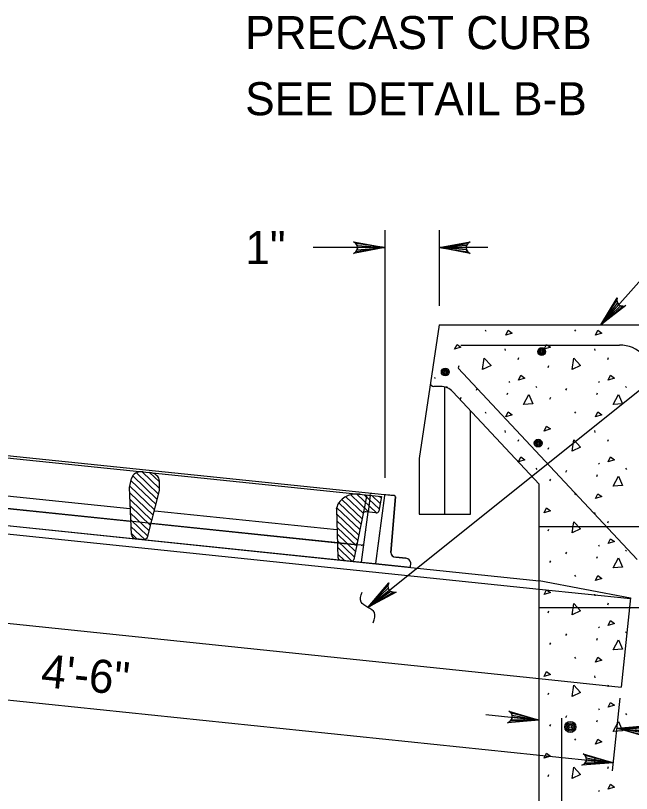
# Model space of a CAD drawing. Extents: x 2.4 to 9.7, y 1.1 to 11.2.
# Drawn here: x 3.54 to 4.657, y 9.657 to 11.069 of the extents above; entities that cross this region are included whole.
import ezdxf

# ---------------------------------------------------------------- set-up
doc = ezdxf.new("R2010")
doc.units = 0
for name, color, linetype in [('DETL-DIMS', 7, 'Continuous'), ('DETL-LINE', 7, 'Continuous'), ('DETL-NOTE', 7, 'Continuous'), ('DETL-PATT', 7, 'Continuous')]:
    doc.layers.add(name, color=color, linetype=linetype)

msp = doc.modelspace()

# ---------------------------------------------------------------- linework, layer by layer
at = {"layer": 'DETL-DIMS'}
for p, q in [((4.6016, 10.5079), (4.967, 10.9182)), ((4.2096, 10.6797), (4.2096, 10.2304)), ((4.3082, 10.6797), (4.3082, 10.5422)), ((4.2096, 10.648), (4.0797, 10.648)), ((4.3967, 10.648), (4.3082, 10.648)), ((4.179, 9.9951), (4.8454, 10.5282)), ((2.8155, 9.9012), (4.6246, 9.7131)), ((4.6231, 9.6985), (4.6368, 9.83)), ((4.393, 9.8005), (4.49, 9.7904)), ((4.6311, 9.7757), (4.9644, 9.7411))]:
    msp.add_line(p, q, dxfattribs=at)
for points in [[(4.2096, 10.648), (4.1531, 10.6374), (4.1575, 10.6404), (4.1597, 10.6442), (4.1604, 10.648), (4.1597, 10.6518), (4.1575, 10.6555), (4.1531, 10.6586), (4.2096, 10.648), (4.1575, 10.6555), (4.1597, 10.6518), (4.2096, 10.648), (4.1604, 10.648), (4.1597, 10.6442), (4.2096, 10.648), (4.1575, 10.6404)], [(4.3082, 10.648), (4.3647, 10.6586), (4.3603, 10.6555), (4.3581, 10.6518), (4.3574, 10.648), (4.3581, 10.6442), (4.3603, 10.6404), (4.3647, 10.6374), (4.3082, 10.648), (4.3603, 10.6404), (4.3581, 10.6442), (4.3082, 10.648), (4.3574, 10.648), (4.3581, 10.6518), (4.3082, 10.648), (4.3603, 10.6555)], [(4.6016, 10.5079), (4.6313, 10.5571), (4.6306, 10.5519), (4.632, 10.5477), (4.6344, 10.5447), (4.6376, 10.5426), (4.6419, 10.5418), (4.6471, 10.543), (4.6016, 10.5079), (4.6419, 10.5418), (4.6376, 10.5426), (4.6016, 10.5079), (4.6344, 10.5447), (4.632, 10.5477), (4.6016, 10.5079), (4.6306, 10.5519)], [(4.1798, 9.9955), (4.217, 10.0393), (4.2155, 10.0342), (4.2161, 10.0299), (4.218, 10.0265), (4.2209, 10.024), (4.225, 10.0225), (4.2303, 10.0229), (4.1798, 9.9955), (4.225, 10.0225), (4.2209, 10.024), (4.1798, 9.9955), (4.218, 10.0265), (4.2161, 10.0299), (4.1798, 9.9955), (4.2155, 10.0342)], [(4.49, 9.7904), (4.4327, 9.7857), (4.4374, 9.7883), (4.44, 9.7918), (4.441, 9.7955), (4.4408, 9.7993), (4.4389, 9.8033), (4.4349, 9.8068), (4.49, 9.7904), (4.4389, 9.8033), (4.4408, 9.7993), (4.49, 9.7904), (4.441, 9.7955), (4.44, 9.7918), (4.49, 9.7904), (4.4374, 9.7883)], [(4.6311, 9.7757), (4.6884, 9.7804), (4.6838, 9.7779), (4.6811, 9.7743), (4.6801, 9.7706), (4.6804, 9.7668), (4.6822, 9.7628), (4.6862, 9.7594), (4.6311, 9.7757), (4.6822, 9.7628), (4.6804, 9.7668), (4.6311, 9.7757), (4.6801, 9.7706), (4.6811, 9.7743), (4.6311, 9.7757), (4.6838, 9.7779)], [(4.6246, 9.7131), (4.5673, 9.7084), (4.572, 9.711), (4.5746, 9.7145), (4.5756, 9.7182), (4.5754, 9.7221), (4.5736, 9.7261), (4.5695, 9.7295), (4.6246, 9.7131), (4.5736, 9.7261), (4.5754, 9.7221), (4.6246, 9.7131), (4.5756, 9.7182), (4.5746, 9.7145), (4.6246, 9.7131), (4.572, 9.711)]]:
    msp.add_lwpolyline(points, dxfattribs=at)
msp.add_spline([(4.1885, 9.9672), (4.1911, 9.9855), (4.1667, 10.0048), (4.1685, 10.0227)], degree=3, dxfattribs=at)
at = {"layer": 'DETL-LINE'}
for p, q in [((4.3082, 10.5076), (4.2721, 10.2655)), ((4.3082, 10.5076), (4.7324, 10.5076)), ((4.348, 10.4712), (4.6355, 10.4712)), ((4.6678, 10.0818), (4.3432, 10.4289)), ((4.311, 10.3961), (4.2986, 10.3961)), ((4.3189, 10.1641), (4.3189, 10.395)), ((4.49, 10.2187), (4.3331, 10.3864)), ((4.3656, 10.1641), (4.3656, 10.3516)), ((2.9528, 10.3296), (4.2267, 10.1978)), ((4.2721, 10.2655), (4.2721, 10.1641)), ((3.7591, 10.2391), (3.7995, 10.2005)), ((3.7693, 10.2411), (3.8012, 10.2107)), ((3.783, 10.2399), (3.8011, 10.2227)), ((2.7749, 10.2215), (4.49, 10.0432)), ((4.1545, 10.1091), (3.0052, 10.228)), ((3.7494, 10.2247), (3.7947, 10.1815)), ((3.7524, 10.2336), (3.7971, 10.191)), ((2.8008, 10.2184), (4.2566, 10.0678)), ((3.7472, 10.2149), (3.7922, 10.1719)), ((4.49, 8.8182), (4.49, 10.2187)), ((3.7472, 10.2031), (3.7898, 10.1624)), ((4.1392, 10.1959), (4.1709, 10.1656)), ((4.1481, 10.1992), (4.1809, 10.1679)), ((4.1591, 10.2006), (4.1946, 10.1667)), ((4.1773, 10.1991), (4.1708, 10.1654)), ((4.1726, 10.1996), (4.1998, 10.1736)), ((4.1833, 10.1985), (4.1794, 10.1681)), ((4.1833, 10.1985), (4.1836, 10.2004)), ((4.1865, 10.1981), (4.2017, 10.1836)), ((4.2092, 10.1978), (4.1927, 10.0744)), ((4.2092, 10.1978), (4.1927, 10.0744)), ((4.2004, 10.1967), (4.2036, 10.1936)), ((4.2267, 10.1978), (4.2118, 10.1994)), ((4.229, 10.1957), (4.2207, 10.0943)), ((4.2208, 10.0946), (4.229, 10.1957)), ((3.0173, 10.1815), (4.49, 10.0284)), ((3.7477, 10.1908), (3.7874, 10.1529)), ((4.1263, 10.1845), (4.1668, 10.146)), ((4.1319, 10.191), (4.1688, 10.1558)), ((3.7482, 10.1785), (3.785, 10.1434)), ((3.7487, 10.1661), (3.7825, 10.1339)), ((4.1228, 10.176), (4.1647, 10.1361)), ((4.1676, 10.077), (4.1794, 10.1681)), ((3.7492, 10.1538), (3.7801, 10.1243)), ((4.1227, 10.1643), (4.1626, 10.1262)), ((4.123, 10.1522), (4.1606, 10.1163)), ((4.2721, 10.1641), (4.3656, 10.1641)), ((3.7498, 10.1415), (3.7738, 10.1186)), ((4.1234, 10.14), (4.1585, 10.1065)), ((4.49, 10.1416), (4.7324, 10.1416)), ((3.7503, 10.1292), (3.7608, 10.1191)), ((4.1237, 10.1279), (4.1565, 10.0966)), ((4.1237, 10.1123), (4.1286, 10.1118)), ((4.1241, 10.1157), (4.1544, 10.0867)), ((4.1286, 10.1118), (4.1545, 10.1091)), ((4.1667, 10.1079), (4.1545, 10.1091)), ((4.1244, 10.1035), (4.15, 10.0791)), ((4.1247, 10.0914), (4.1364, 10.0802)), ((4.2477, 10.0841), (4.2298, 10.086)), ((4.2298, 10.086), (4.2477, 10.0841)), ((4.2566, 10.0678), (4.2568, 10.0759)), ((4.49, 10.0441), (4.6558, 10.0126)), ((4.49, 10.0284), (4.6556, 10.0112)), ((3.0173, 10.0188), (4.49, 9.8657)), ((4.6558, 10.0126), (4.6389, 9.8503)), ((4.49, 9.9951), (4.7324, 9.9951)), ((4.49, 9.8657), (4.6389, 9.8503)), ((4.531, 8.6833), (4.531, 9.7941))]:
    msp.add_line(p, q, dxfattribs=at)
msp.add_lwpolyline([(4.1927, 10.0744), (4.2566, 10.0678), (4.2568, 10.0759)], dxfattribs=at)
for centre, radius in [((4.4944, 10.4593), 0.00707), ((4.4944, 10.4593), 0.0053), ((4.4944, 10.4593), 0.00354), ((4.4944, 10.4593), 0.00177), ((4.3195, 10.4221), 0.00707), ((4.3195, 10.4221), 0.0053), ((4.3195, 10.4221), 0.00354), ((4.3195, 10.4221), 0.00177), ((4.4881, 10.2932), 0.00707), ((4.4881, 10.2932), 0.0053), ((4.4881, 10.2932), 0.00354), ((4.4881, 10.2932), 0.00177), ((4.5464, 9.7781), 0.0101), ((4.5464, 9.7781), 0.00758), ((4.5464, 9.7781), 0.00505), ((4.5464, 9.7781), 0.00253)]:
    msp.add_circle(centre, radius, dxfattribs=at)
for centre, radius, start, end in [((4.6355, 10.4106), 0.0606, 0, 90), ((4.2986, 10.4021), 0.00606, 171.5077, 270), ((4.311, 10.3657), 0.0303, 43.0821, 90)]:
    msp.add_arc(centre, radius, start, end, dxfattribs=at)
for centre, major_axis, start_param, end_param in [((4.1861, 10.2001), (0.00246, -0.00025), 1.56959, 3.120609), ((4.2116, 10.1975), (0.00246, -0.00025), 1.56959, 3.117735), ((4.2116, 10.1975), (0.00246, -0.00025), 1.56959, 3.117735), ((4.2265, 10.1959), (0.00246, -0.00025), 0.016408, 1.56959), ((4.2265, 10.1959), (0.00246, -0.00025), 0.016408, 1.56959), ((4.129, 10.1156), (0.00492, -0.0005), 3.227653, 4.711182), ((4.1548, 10.1129), (0.00492, -0.0005), 4.711182, 6.215411), ((4.1671, 10.1117), (0.00492, -0.0005), 4.711182, 6.261981), ((4.2306, 10.0936), (0.00984, -0.00101), 3.144452, 4.711182), ((4.2306, 10.0936), (0.00984, -0.00101), 3.171548, 4.711182), ((4.2469, 10.0765), (0.00984, -0.00101), 0.060618, 1.56959), ((4.2469, 10.0765), (0.00984, -0.00101), 0.060618, 1.56959)]:
    msp.add_ellipse(centre, major_axis=major_axis, ratio=0.773781, start_param=start_param, end_param=end_param, dxfattribs=at)
at = {"layer": 'DETL-NOTE'}
for p, q in [((2.9746, 10.3235), (4.2041, 10.1963)), ((3.7468, 10.2129), (3.7504, 10.2292)), ((3.8012, 10.2072), (3.8011, 10.224)), ((3.4169, 10.2085), (3.7475, 10.1743)), ((3.7504, 10.1272), (3.7468, 10.2129)), ((3.7801, 10.1241), (3.8012, 10.2072)), ((3.8012, 10.2072), (3.8012, 10.2072)), ((4.2041, 10.1963), (4.199, 10.1697)), ((4.2267, 10.1978), (4.2267, 10.1978)), ((3.4117, 10.186), (3.747, 10.1513)), ((4.1236, 10.1857), (4.1236, 10.1857)), ((4.1228, 10.1355), (3.7925, 10.1697)), ((4.1224, 10.174), (4.123, 10.1766)), ((4.1224, 10.174), (4.1249, 10.0849)), ((4.1224, 10.174), (4.1224, 10.174)), ((4.1708, 10.1654), (4.1535, 10.0821)), ((4.1937, 10.1666), (4.1761, 10.1684)), ((4.2054, 10.161), (4.2054, 10.161)), ((3.7883, 10.147), (4.1237, 10.1123)), ((4.1713, 10.1422), (4.1713, 10.1422)), ((4.1768, 10.1348), (4.1768, 10.1348)), ((4.1975, 10.1328), (4.1975, 10.1328)), ((4.1982, 10.1272), (4.1982, 10.1272)), ((3.7695, 10.1182), (3.7594, 10.1192)), ((4.1274, 10.1084), (4.1274, 10.1084)), ((4.1571, 10.1172), (4.1571, 10.1172)), ((4.2003, 10.1123), (4.2003, 10.1123)), ((4.22, 10.1102), (4.22, 10.1102)), ((4.1295, 10.081), (4.1482, 10.079)), ((4.2477, 10.0841), (4.2477, 10.0841)), ((4.2566, 10.0678), (4.2566, 10.0678))]:
    msp.add_line(p, q, dxfattribs=at)
for centre, major_axis, start_param, end_param in [((3.7698, 10.2259), (0.0197, -0.002), 1.56959, 3.05312), ((3.7813, 10.2247), (0.0197, -0.002), 0.08606, 1.56959), ((4.1619, 10.1699), (0.0394, -0.004), 1.56959, 3.05312), ((4.1757, 10.1646), (0.00492, -0.0005), 1.56959, 3.073818), ((4.1941, 10.1704), (0.00492, -0.0005), 4.711182, 6.215411), ((3.7602, 10.1268), (0.00984, -0.00101), 3.223527, 4.711182), ((3.7703, 10.1258), (0.00984, -0.00101), 4.711182, 6.198838), ((4.1299, 10.0848), (0.00492, -0.0005), 3.227653, 4.711182), ((4.1486, 10.0828), (0.00492, -0.0005), 4.711182, 6.215411)]:
    msp.add_ellipse(centre, major_axis=major_axis, ratio=0.773781, start_param=start_param, end_param=end_param, dxfattribs=at)
at = {"layer": 'DETL-PATT'}
for p, q in [((4.3917, 10.4986), (4.3933, 10.4962)), ((4.5542, 10.4986), (4.5558, 10.4962)), ((4.4279, 10.4644), (4.4283, 10.4612)), ((4.5904, 10.4644), (4.5908, 10.4612)), ((4.4519, 10.445), (4.4531, 10.4483)), ((4.6144, 10.445), (4.6156, 10.4483)), ((4.3438, 10.4306), (4.345, 10.4338)), ((4.5063, 10.4306), (4.5075, 10.4338)), ((4.4348, 10.4052), (4.436, 10.4032)), ((4.5973, 10.4052), (4.5985, 10.4032)), ((4.3216, 10.3959), (4.3233, 10.3939)), ((4.376, 10.3891), (4.3776, 10.3923)), ((4.4841, 10.3959), (4.4858, 10.3939)), ((4.5385, 10.3891), (4.5401, 10.3923)), ((4.6466, 10.3959), (4.6483, 10.3939)), ((4.347, 10.3731), (4.3486, 10.3763)), ((4.4319, 10.3812), (4.4332, 10.3844)), ((4.5095, 10.3731), (4.5111, 10.3763)), ((4.5944, 10.3812), (4.5957, 10.3844)), ((4.3917, 10.3502), (4.3933, 10.3477)), ((4.5542, 10.3502), (4.5558, 10.3477)), ((4.4279, 10.3159), (4.4283, 10.3127)), ((4.5904, 10.3159), (4.5908, 10.3127)), ((4.4519, 10.2966), (4.4531, 10.2998)), ((4.6144, 10.2966), (4.6156, 10.2998)), ((4.5063, 10.2821), (4.5075, 10.2853)), ((4.5973, 10.2568), (4.5985, 10.2547)), ((4.4841, 10.2475), (4.4858, 10.2455)), ((4.5385, 10.2407), (4.5401, 10.2439)), ((4.5944, 10.2327), (4.5957, 10.2359)), ((4.6466, 10.2475), (4.6483, 10.2455)), ((4.5095, 10.2247), (4.5111, 10.2279)), ((4.5542, 10.2017), (4.5558, 10.1993)), ((4.5904, 10.1675), (4.5908, 10.1643)), ((4.6144, 10.1482), (4.6156, 10.1514)), ((4.5063, 10.1337), (4.5075, 10.1369)), ((4.5973, 10.1083), (4.5985, 10.1063)), ((4.5385, 10.0922), (4.5401, 10.0954)), ((4.6466, 10.0991), (4.6483, 10.097)), ((4.5944, 10.0843), (4.5957, 10.0875)), ((4.5095, 10.0762), (4.5111, 10.0794)), ((4.5542, 10.0533), (4.5558, 10.0509)), ((4.5904, 10.0191), (4.5908, 10.0158)), ((4.6144, 9.9997), (4.6156, 10.003)), ((4.5063, 9.9852), (4.5075, 9.9885)), ((4.5973, 9.9599), (4.5985, 9.9579)), ((4.5385, 9.9438), (4.5401, 9.947)), ((4.5944, 9.9358), (4.5957, 9.9391)), ((4.6466, 9.9506), (4.6483, 9.9486)), ((4.5095, 9.9278), (4.5111, 9.931)), ((4.5542, 9.9048), (4.5558, 9.9024)), ((4.5904, 9.8706), (4.5908, 9.8674)), ((4.6144, 9.8513), (4.6156, 9.8545)), ((4.5063, 9.8368), (4.5075, 9.84)), ((4.5385, 9.7953), (4.5401, 9.7986)), ((4.5973, 9.8114), (4.5985, 9.8094)), ((4.6466, 9.8022), (4.6483, 9.8002)), ((4.5944, 9.7874), (4.5957, 9.7906)), ((4.5095, 9.7794), (4.5111, 9.7826)), ((4.5542, 9.7564), (4.5558, 9.754)), ((4.5904, 9.7222), (4.5908, 9.719)), ((4.6144, 9.7029), (4.6156, 9.7061)), ((4.5063, 9.6884), (4.5075, 9.6916)), ((4.5973, 9.663), (4.5985, 9.661))]:
    msp.add_line(p, q, dxfattribs=at)
for points in [[(4.4295, 10.4893), (4.4336, 10.4982), (4.4408, 10.493), (4.4295, 10.4893)], [(4.592, 10.4893), (4.5961, 10.4982), (4.6033, 10.493), (4.592, 10.4893)], [(4.3365, 10.4636), (4.341, 10.4724), (4.3478, 10.4672), (4.3365, 10.4636)], [(4.499, 10.4636), (4.5035, 10.4724), (4.5103, 10.4672), (4.499, 10.4636)], [(4.3873, 10.4269), (4.3901, 10.4475), (4.4026, 10.4342), (4.3873, 10.4269)], [(4.5498, 10.4269), (4.5526, 10.4475), (4.5651, 10.4342), (4.5498, 10.4269)], [(4.3, 10.4123), (4.3015, 10.4112), (4.2998, 10.4107)], [(4.4523, 10.4076), (4.4568, 10.4165), (4.464, 10.4112), (4.4523, 10.4076)], [(4.6148, 10.4076), (4.6193, 10.4165), (4.6265, 10.4112), (4.6148, 10.4076)], [(4.4616, 10.3634), (4.4713, 10.3816), (4.4785, 10.3646), (4.4616, 10.3634)], [(4.6241, 10.3634), (4.6338, 10.3816), (4.641, 10.3646), (4.6241, 10.3634)], [(4.4295, 10.3409), (4.4336, 10.3498), (4.4408, 10.3445), (4.4295, 10.3409)], [(4.592, 10.3409), (4.5961, 10.3498), (4.6033, 10.3445), (4.592, 10.3409)], [(4.499, 10.3151), (4.5035, 10.324), (4.5103, 10.3188), (4.499, 10.3151)], [(4.5498, 10.2785), (4.5526, 10.299), (4.5651, 10.2857), (4.5498, 10.2785)], [(4.4523, 10.2592), (4.4568, 10.268), (4.464, 10.2628), (4.4523, 10.2592)], [(4.6148, 10.2592), (4.6193, 10.268), (4.6265, 10.2628), (4.6148, 10.2592)], [(4.6241, 10.215), (4.6338, 10.2331), (4.641, 10.2162), (4.6241, 10.215)], [(4.592, 10.1925), (4.5961, 10.2013), (4.6033, 10.1961), (4.592, 10.1925)], [(4.499, 10.1667), (4.5035, 10.1755), (4.5103, 10.1703), (4.499, 10.1667)], [(4.5498, 10.1301), (4.5526, 10.1506), (4.5651, 10.1373), (4.5498, 10.1301)], [(4.6148, 10.1107), (4.6193, 10.1196), (4.6265, 10.1144), (4.6148, 10.1107)], [(4.6241, 10.0666), (4.6338, 10.0847), (4.641, 10.0678), (4.6241, 10.0666)], [(4.592, 10.044), (4.5961, 10.0529), (4.6033, 10.0476), (4.592, 10.044)], [(4.499, 10.0183), (4.5035, 10.0271), (4.5103, 10.0219), (4.499, 10.0183)], [(4.5498, 9.9816), (4.5526, 10.0022), (4.5651, 9.9889), (4.5498, 9.9816)], [(4.6148, 9.9623), (4.6193, 9.9712), (4.6265, 9.9659), (4.6148, 9.9623)], [(4.6241, 9.9181), (4.6338, 9.9362), (4.641, 9.9193), (4.6241, 9.9181)], [(4.592, 9.8956), (4.5961, 9.9044), (4.6033, 9.8992), (4.592, 9.8956)], [(4.499, 9.8698), (4.5035, 9.8787), (4.5103, 9.8734), (4.499, 9.8698)], [(4.5498, 9.8332), (4.5526, 9.8537), (4.5651, 9.8404), (4.5498, 9.8332)], [(4.6148, 9.8139), (4.6193, 9.8227), (4.6265, 9.8175), (4.6148, 9.8139)], [(4.6241, 9.7697), (4.6338, 9.7878), (4.641, 9.7709), (4.6241, 9.7697)], [(4.592, 9.7471), (4.5961, 9.756), (4.6033, 9.7508), (4.592, 9.7471)], [(4.499, 9.7214), (4.5035, 9.7302), (4.5103, 9.725), (4.499, 9.7214)], [(4.5498, 9.6847), (4.5526, 9.7053), (4.5651, 9.692), (4.5498, 9.6847)], [(4.6148, 9.6654), (4.6193, 9.6743), (4.6265, 9.669), (4.6148, 9.6654)]]:
    msp.add_lwpolyline(points, dxfattribs=at)

# ---------------------------------------------------------------- texts
at = {"layer": 'DETL-NOTE'}
for s, p in [('PRECAST CURB', (3.9565, 11.0082)), ('SEE DETAIL B-B', (3.9565, 10.8882)), ('1"', (3.9567, 10.618))]:
    msp.add_text(s, height=0.06, dxfattribs=at).set_placement(p)
msp.add_text('4\'-6"', height=0.06, rotation=354.3661, dxfattribs=at).set_placement((3.5844, 9.8509))

doc.saveas('drawing.dxf')
